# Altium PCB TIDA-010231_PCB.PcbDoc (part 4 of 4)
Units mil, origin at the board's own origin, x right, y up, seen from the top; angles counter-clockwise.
Board outline 3937.01 x 3740.16 mil, 4 copper layers (Top Layer, Signal Layer 1, Signal Layer 2, Bottom Layer), stack 65.355 mil thick; 295 components, 163 nets, 818 pads, 213 vias.
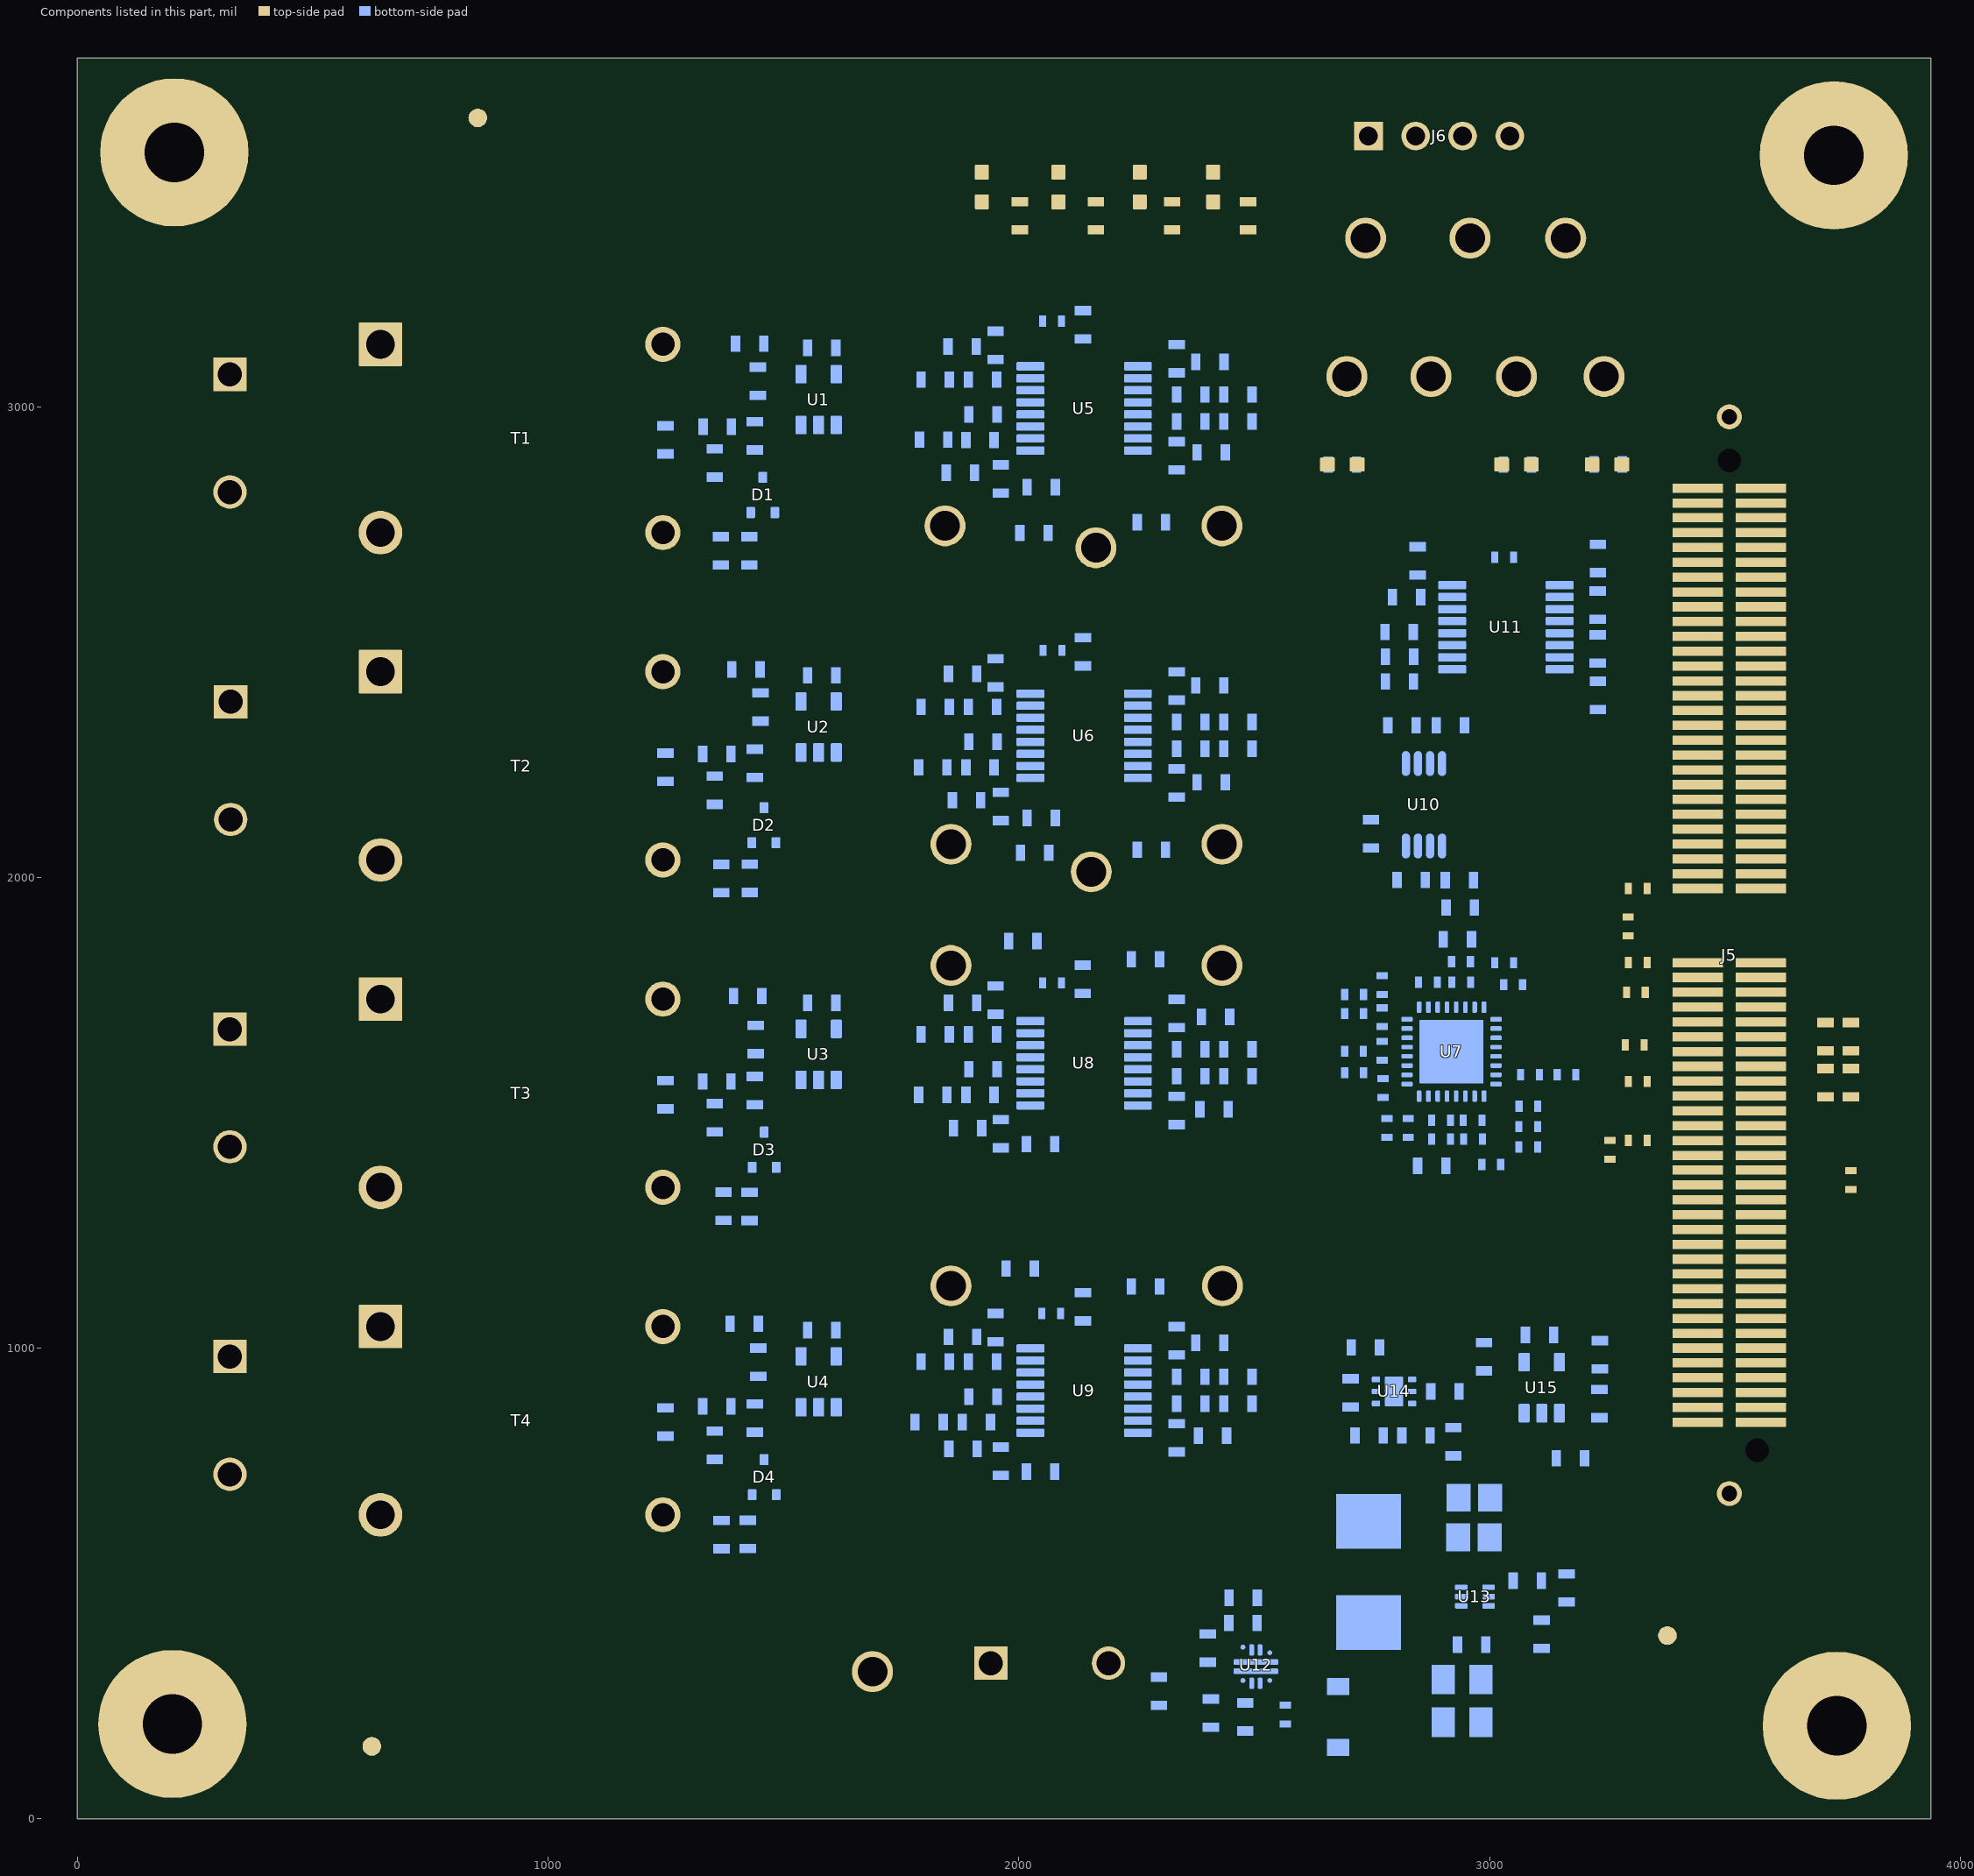
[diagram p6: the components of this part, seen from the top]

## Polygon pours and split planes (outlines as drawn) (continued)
NetC73_2 on Bottom Layer "BOTTOM_LAYER_NETC73_2_P401" (solid, remove dead copper, pour order 401): 2953.13,478.2 2953.13,466.26 2953.1,466.23 2952.97,466.36 2922.81,466.36 2840.31,383.86 2840.31,359.94 2692.08,359.94 2692,359.87 2692,477.12
GND on Bottom Layer "BOTTOM_LAYER_GND_P402" (solid, remove dead copper, pour order 402): 3097.94,573.68 3098.31,573.32 3143.73,573.32 3143.73,710.59 2976.95,710.59 2976.95,551.64 2894.76,551.64 2894.76,514.52 2922.32,486.96 2953.31,486.96 2957.63,482.64 2957.63,165.13 3191.88,165.13 3191.88,390.3 3098.57,390.3 3050.14,438.73 2976.95,438.73 2976.95,505.66 3029.93,505.66
NetC84_1 on Bottom Layer "BOTTOM_LAYER_NETC84_1_P398" (solid, pour order 398): 2553.65,235.54 2553.65,248.95 2525.4,277.19 2525.4,298.9 2557.77,298.9 2579.89,276.77 2579.89,235.54
GND on Bottom Layer "BOTTOM_LAYER_GND_P425" (solid, remove dead copper, pour order 425): 3307.87,2568.6 3221.36,2568.6 3181.29,2528.53 3111.39,2528.53 3111.39,2606.57 3108.88,2609.08 2963.66,2609.08 2963.66,2456.53 2964.7,2455.49 3106.68,2455.49 3106.68,2495.25 3123.2,2511.77 3199.78,2511.77 3222,2489.55 3308.14,2489.55
3V3 on Bottom Layer "BOTTOM_LAYER_3V3_P420" (solid, remove dead copper, pour order 420): 3114.42,1035.32 3104.82,1044.92 3104.82,1093.03 3260.4,1093.03 3260.4,993.13 3218.44,993.13 3172.98,947.67 3126.31,947.67 3114.42,959.57
GND on Bottom Layer "BOTTOM_LAYER_GND_P419" (solid, remove dead copper, pour order 419): 3024.94,1916.26 3024.94,2342.01 2889.01,2342.01 2889.01,2206.39 2726.94,2206.39 2726.94,2110.57 2955.87,2110.57 2976.96,2089.48 2974.77,2087.3 2974.77,2013.76 2955.87,2013.76 2955.87,1916.26
2V5 on Bottom Layer "BOTTOM_LAYER_2V5_P416" (solid, pour order 416): 2874.5,1712.44 2874.5,1745.75 2854.89,1765.36 2854.89,1804.19 2840.69,1804.19 2840.69,1718.34 2846.6,1712.44
NetC77_1 on Bottom Layer "BOTTOM_LAYER_NETC77_1_P411" (solid, pour order 411): 2826.94,887.91 2827.02,887.98 2847.15,887.98 2892.76,842.37 2940.86,842.37 2940.86,794.84 2840.24,794.84 2840.24,852.84 2826.41,866.66 2826.41,888.65
5V25 on Bottom Layer "Bottom Layer-5V25" (solid, pour order 410): 2641.24,568.78 2959.4,568.78 2959.4,737.66 3172.98,737.66 3172.98,790.25 2860.12,790.25 2860.12,744.11 2643.11,744.11 2641.24,745.98
GND on Bottom Layer "BOTTOM_LAYER_GND_P407" (solid, remove dead copper, pour order 407): 3296.14,892.1 3135.44,892.1 3122.55,879.21 3122.55,843.46 3100.2,843.46 3098.71,844.95 3099.91,846.14 3099.91,879.81 3090.07,889.64 2967.92,889.64 2967.92,980.2 3047.47,980.2 3047.47,947.73 3059.09,936.11 3171.7,936.11 3199.43,963.84 3296.14,963.84
GND on Bottom Layer "BOTTOM_LAYER_GND_P403" (solid, pour order 403): 2761.59,859.99 2778.46,876.86 2778.46,915.6 2764.8,929.27 2750.14,929.27 2750.14,1021.18 2817.62,1021.18 2817.62,861.56 2826.94,852.23 2826.53,851.82 2826.53,759.79 2761.59,759.79
NetC74_1 on Bottom Layer "BOTTOM_LAYER_NETC74_1_P399" (solid, remove dead copper, pour order 399): 2930.18,337.51 2944.06,351.39 2944.06,438.81 2952.84,447.59 2951.8,448.64 2951.8,459.29 2927.81,459.29 2849.59,381.07 2849.59,337.51 2768.99,337.51 2750.61,319.13 2456.57,319.13 2456.57,307.57 2589.28,307.57 2687.97,208.88 2809.07,208.88 2852.85,165.1 2930.18,165.1
NetC83_1 on Bottom Layer "BOTTOM_LAYER_NETC83_1_P395" (solid, pour order 395): 2435,241.35 2388.21,241.35 2388.21,261.45 2426.51,299.75 2479.83,299.75 2481.8,297.78 2481.8,288.14
GND on Bottom Layer "BOTTOM_LAYER_GND_P397" (solid, remove dead copper, pour order 397): 2541.54,221.76 2541.54,252.04 2517.1,276.48 2517.1,298.54 2515.9,299.75 2509.55,299.75 2508.37,298.57 2508.37,208.88 2068.49,208.88 2004.61,272.77 2004.61,374.45 1881.85,374.45 1879.82,122.41 2794.06,122.41 2794.06,189.04 2622.89,189.04 2590.18,221.76
Vin on Bottom Layer "BOTTOM_LAYER_VIN_P393" (solid, remove dead copper, pour order 393): 2149.06,372.76 2153.22,368.6 2407.9,368.6 2437.56,338.94 2544.79,338.94 2544.79,327.11 2544.75,327.07 2544.56,327.26 2437.47,327.26 2400.11,289.91 2149.06,289.91
NetR104_1 on Bottom Layer "BOTTOM_LAYER_NETR104_1_P392" (solid, remove dead copper, pour order 392): 2480.94,347.29 2480.67,347.57 2435.94,347.57 2404.86,378.66 2381.4,378.66 2381.4,429.17 2458.17,429.17 2458.17,393.08 2480.94,370.32
GND on Bottom Layer "BOTTOM_LAYER_GND_P391" (solid, remove dead copper, pour order 391): 2115.4,1763.27 2206.14,1763.27 2206.14,1414.61 2066.85,1414.61 2066.85,1642.32 2115.4,1690.86
GND on Bottom Layer "BOTTOM_LAYER_GND_P390" (solid, remove dead copper, pour order 390): 2115.4,1064.46 2206.14,1064.46 2206.14,719.09 2066.85,719.09 2066.85,946.81 2115.4,995.35
GND on Bottom Layer "BOTTOM_LAYER_GND_P387" (solid, remove dead copper, pour order 387): 2115.4,2459.2 2206.14,2459.2 2206.14,2106.56 2066.85,2106.56 2066.85,2337.83 2115.4,2386.37
GND on Bottom Layer "BOTTOM_LAYER_GND_P386" (solid, remove dead copper, pour order 386): 2115.4,3151 2206.14,3151 2206.14,2810.89 2066.85,2810.89 2066.85,3033.34 2115.4,3081.88
CH4- on Bottom Layer "BOTTOM_LAYER_CH4-_P381" (solid, remove dead copper, pour order 381): 285.97,769.93 692.85,769.93 692.85,596.87 285.97,596.87
CH3- on Bottom Layer "BOTTOM_LAYER_CH3-_P377" (solid, remove dead copper, pour order 377): 285.97,1465.47 692.85,1465.47 692.85,1292.41 285.97,1292.41
CH1- on Bottom Layer "BOTTOM_LAYER_CH1-_P373" (solid, remove dead copper, pour order 373): 285.97,2856.55 692.85,2856.55 692.85,2683.48 285.97,2683.48
CH2- on Bottom Layer "BOTTOM_LAYER_CH2-_P369" (solid, remove dead copper, pour order 369): 287.59,2161.01 694.47,2161.01 694.47,1987.94 287.59,1987.94
CH4+ on Bottom Layer "BOTTOM_LAYER_CH4+_P362" (solid, remove dead copper, pour order 362): 287.4,944.88 694.29,944.88 694.29,1091.55 287.4,1091.55
CH3+ on Bottom Layer "BOTTOM_LAYER_CH3+_P358" (solid, remove dead copper, pour order 358): 287.4,1640.42 694.29,1640.42 694.29,1787.09 287.4,1787.09
CH2+ on Bottom Layer "BOTTOM_LAYER_CH2+_P354" (solid, remove dead copper, pour order 354): 289.03,2335.96 695.91,2335.96 695.91,2482.63 289.03,2482.63
CH1+ on Bottom Layer "BOTTOM_LAYER_CH1+_P349" (solid, remove dead copper, pour order 349): 287.4,3031.5 694.29,3031.5 694.29,3178.17 287.4,3178.17
CT1_OUT- on Bottom Layer "BOTTOM_LAYER_CT1_OUT-_P348" (solid, remove dead copper, pour order 348): 1176.65,2650.42 1176.65,2908.7 1311.07,2908.7 1352.98,2866.79 1370.9,2866.79 1422.07,2815.62 1495.51,2815.62 1495.51,2710 1421.19,2710 1327.09,2710 1327.09,2649.53
5V on Signal Layer 2 "SIGNAL_LAYER_2_5V_P191" (solid, pour order 191): 2906.42,1484.47 2917.21,1495.26 2917.21,1871.26 2771.65,1871.26 2771.65,3157.92 1556.97,3159.01 1556.97,809.33 2906.42,809.33
5V25 on Signal Layer 2 "SIGNAL_LAYER_2_5V25_P421" (solid, pour order 421): 2934.1,744.11 3830.1,744.11 3874.02,788.03 3874.02,3017.36 3748.66,3017.36 3748.66,852.84 3245.38,852.84 3195.2,802.66 2932.49,802.66
3V3 on Signal Layer 2 "Signal Layer 2-3V3" (solid, remove dead copper, pour order 438): 1185.72,719.09 1378.06,719.09 1386.28,727.31 1362.53,751.06 1362.53,3373.03 3014.91,3373.03 3039.1,3348.84 3039.1,1886.4 2926.43,1773.73 2926.43,858.59 3737.8,858.59 3737.8,2974.15 3170.67,3541.27 1185.72,3541.27
2V5 on Signal Layer 2 "SIGNAL_LAYER_2_2V5_P192" (solid, pour order 192): 3024.28,2251.1 3024.28,3344.49 1386.79,3344.49 1396.11,480.32 1548.67,480.32 1548.67,3173.13 2794.16,3173.13 2794.16,1881.25 3024.28,1881.25
CH4- on Signal Layer 2 "SIGNAL_LAYER_2_CH4-_P379" (solid, remove dead copper, pour order 379): 286.73,769.17 693.62,769.17 693.62,596.1 286.73,596.1
CH3- on Signal Layer 2 "SIGNAL_LAYER_2_CH3-_P375" (solid, remove dead copper, pour order 375): 286.73,1464.7 693.62,1464.7 693.62,1291.64 286.73,1291.64
CH1- on Signal Layer 2 "SIGNAL_LAYER_2_CH1-_P371" (solid, remove dead copper, pour order 371): 286.73,2855.78 693.62,2855.78 693.62,2682.72 286.73,2682.72
CH2- on Signal Layer 2 "SIGNAL_LAYER_2_CH2-_P367" (solid, remove dead copper, pour order 367): 288.36,2160.24 695.24,2160.24 695.24,1987.18 288.36,1987.18
CH4+ on Signal Layer 2 "SIGNAL_LAYER_2_CH4+_P364" (solid, remove dead copper, pour order 364): 287.4,944.88 694.29,944.88 694.29,1091.55 287.4,1091.55
CH3+ on Signal Layer 2 "SIGNAL_LAYER_2_CH3+_P360" (solid, remove dead copper, pour order 360): 287.4,1640.42 694.29,1640.42 694.29,1787.09 287.4,1787.09
CH2+ on Signal Layer 2 "SIGNAL_LAYER_2_CH2+_P356" (solid, remove dead copper, pour order 356): 289.03,2335.96 695.91,2335.96 695.91,2482.63 289.03,2482.63
CH1+ on Signal Layer 2 "SIGNAL_LAYER_2_CH1+_P352" (solid, remove dead copper, pour order 352): 287.4,3031.5 694.29,3031.5 694.29,3178.17 287.4,3178.17
GND on Signal Layer 1 "Signal Layer 1-GND" (solid, pour order 198): 3263.35,3623.8 3874.02,3008.47 3874.02,683.71 3229.68,39.37 1185.72,39.37 1183.61,3623.8
CH4- on Signal Layer 1 "SIGNAL_LAYER_1_CH4-_P378" (solid, remove dead copper, pour order 378): 285.78,770.34 692.66,770.34 692.66,597.28 285.78,597.28
CH3- on Signal Layer 1 "SIGNAL_LAYER_1_CH3-_P374" (solid, remove dead copper, pour order 374): 285.78,1465.88 692.66,1465.88 692.66,1292.82 285.78,1292.82
CH1- on Signal Layer 1 "SIGNAL_LAYER_1_CH1-_P370" (solid, remove dead copper, pour order 370): 285.78,2856.96 692.66,2856.96 692.66,2683.89 285.78,2683.89
CH2- on Signal Layer 1 "SIGNAL_LAYER_1_CH2-_P366" (solid, remove dead copper, pour order 366): 287.4,2161.42 694.29,2161.42 694.29,1988.35 287.4,1988.35
CH4+ on Signal Layer 1 "SIGNAL_LAYER_1_CH4+_P363" (solid, remove dead copper, pour order 363): 287.4,944.88 694.29,944.88 694.29,1091.55 287.4,1091.55
CH3+ on Signal Layer 1 "SIGNAL_LAYER_1_CH3+_P359" (solid, remove dead copper, pour order 359): 287.4,1640.42 694.29,1640.42 694.29,1787.09 287.4,1787.09
CH2+ on Signal Layer 1 "SIGNAL_LAYER_1_CH2+_P355" (solid, remove dead copper, pour order 355): 289.03,2335.96 695.91,2335.96 695.91,2482.63 289.03,2482.63
CH1+ on Signal Layer 1 "SIGNAL_LAYER_1_CH1+_P351" (solid, remove dead copper, pour order 351): 287.4,3031.5 694.29,3031.5 694.29,3178.17 287.4,3178.17

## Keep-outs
Keep-Out Layer:
  text ".Layer_Name" at 577,-858.49 h60

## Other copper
Top Layer:
  text ".Layer_Name" at 577,-858.49 h60
Signal Layer 1:
  text ".Layer_Name" at 577,-858.49 h60
Signal Layer 2:
  text ".Layer_Name" at 577,-858.49 h60
Bottom Layer:
  text ".Layer_Name" at 577,-858.49 h60

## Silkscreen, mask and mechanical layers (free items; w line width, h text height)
Top Overlay:
  text "TIDA-0100231" at 1822.31,3620.72 h108.27
  text "Danger High Voltage" at 406.07,3344.49 h78.74
  text "CH1: 1kV/10A max" at 141.73,3259.75 h78.74
  text "5V" at 2651.87,2924.35 h39.37
  text "2.5V" at 2817.31,2924.35 h39.37
  text "3.3V" at 3006.88,2924.35 h39.37
  text "5.3V" at 3199.55,2924.35 h39.37
  text "CH1_ / Filt_In" at 1554.64,2629.16 h39.37
  text "GND" at 2119.72,2572.98 h39.37
  text "CH2: 1kV/10A max" at 141.73,2551.18 h78.74
  text "CH1_ / Filt_Out" at 2332.52,2521.46 h39.37
  text "CH2_ / Filt_Out" at 2512.72,2039.46 h39.37
  text "CH2_ / Filt_In" at 1574.69,1945.72 h39.37
  text "GND" at 2105.15,1881.26 h39.37
  text "CH3: 1kV/10A max" at 141.73,1858.27 h78.74
  text "CH3_ / Filt_In" at 1937.16,1767.93 h39.37
  text "CH3_ / Filt_Out" at 2516.27,1703.18 h39.37
  text "CH4: 1kV/10A max" at 141.73,1157.48 h78.74
  text "CH4_ / Filt_In" at 1945.7,1071.85 h39.37
  text "CH4_ / Filt_Out" at 2512.72,1067.69 h39.37
  text "GND" at 1866.22,542.58 h39.37
  text "Vin:  / 8V to 16V" at 2162.58,530.3 h39.37
  text "GND" at 1631,171.48 h39.37
  text ".Layer_Name" at 577,-858.49 h60
Bottom Overlay:
  lines w10: 1786.21,2398.13 1904.11,2398.13 1911.17,2391.07 1911.17,2389.58 ; 1786.21,3109.67 1804.3,3091.57 1843.07,3091.94 1887.4,3091.94 ; 1793.76,1701.72 1874.15,1701.71 1879.45,1696.41 1879.45,1694.48 ; 1810.8,2893.82 1902.68,2893.82 1908.15,2893.82 1913.78,2899.45 ; 1818.77,2192.79 1818.77,2192.21 1826.91,2200.35 1909.45,2200.35 ; 1834.65,2397.92 1834.85,2398.13 ; 1840.16,1498.18 1851.04,1509.06 1895.2,1509.06 ; 1922.2,2051.46 1922.2,2085.08 ; 1924.38,2087.26 1928.73,2091.61 1930.91,2093.79 ; 1934.15,2097.27 1936.33,2099.44 ; 1964.9,2753.55 1971.08,2759.73 1971.08,2791.97 ; 2371.04,1662.98 2377.27,1669.21 2379.34,1669.21 2389.35,1669.21 2457.27,1669.21 ; 2374.36,971.23 2450.11,971.23 ; 2375.46,850.54 2444.8,850.54 ; 2379.99,2359.94 2437.91,2359.94 2472.76,2394.79 ; 2386.49,2242.42 2451.2,2242.42 2464.97,2228.65 ; 2388.21,436.23 2404.22,420.22 2422.73,420.22 ; 2408.31,3056.88 2447.32,3056.88 2483.18,3092.74 ; 2410.29,971.23 2450.11,971.23 ; 2411.41,1550.24 2411.41,1549.92 2423.62,1537.71 2463.97,1537.71 2483.77,1517.91 ; 2412.64,2939.17 2450.38,2939.17 2457.27,2932.28 ; 2479.36,1522.32 2488.18,1513.5 ; 2483.11,1017.79 2483.11,1004.23 ; 2483.96,969.11 2492.42,969.11 2509.75,986.45 ; 2516.32,1583.24 2552.31,1583.24 2554.79,1580.76 2554.79,1570.41 ; 2548.06,1720.6 2567.31,1701.35 2664.89,1701.35 2679.06,1687.71 2748.99,1687.71 ; 2585.2,1953.01 2586.61,1951.6 2491.32,1951.6 2491.32,1833.38 2520.26,1833.38 2698.23,1833.38 2702.8,1837.95 2702.8,1966.48 2702.8,1975.79 2702.8,2031.65 2586.73,2031.65 ; 2585.91,1952.31 2585.91,2030.83 ; 2690.47,1662.98 2738.42,1662.98 2743.67,1657.73 2746.63,1657.73 ; 2704.01,1921.26 2702.8,1920.04 2753.14,1920.04 2753.14,1917.24 2753.4,1917.24 2818.26,1852.38 2788.63,1852.61 ; 2709.22,1497.38 2720.09,1508.26 2727.05,1508.26 2748.04,1526.9 ; 2739.47,1310.7 2931.57,1310.7 2949.93,1329.07 2949.93,1376.41 2949.93,1417.61 ; 2763.78,1819.34 2770.33,1812.79 2770.33,1812.56 2770.33,1808.82 ; 2768.36,1985.89 2780.17,1985.89 ; 2817.23,1883.41 2817.54,1852.21 ; 2851.34,759.79 2851.34,780.27 ; 2852.49,998.97 2852.49,968.26 2880.38,940.37 ; 2854.55,355.33 2867.1,367.89 2910,367.89 ; 2949.93,1417.97 2949.93,1417.66 ; 3053.28,703.95 3163.43,703.95 ; 3059.42,581.22 3163.43,581.22 ; 3094.4,1639.56 3094.5,1639.56 3098.07,1635.99 3098.07,1610.57 ; 3123.13,1517.94 3156.71,1484.36 ; 3123.53,1472.38 3139.22,1472.38 3152.94,1458.66 3162.82,1448.78 ; 3168.84,1601.45 3229.93,1662.39 ; 2450.11,971.23 2483.11,1004.23 ; 2450.11,971.23 2483.11,1004.23 ; 2949.93,1417.61 2937.83,1405.51 2949.93,1417.61 ; 2949.93,1417.61 2949.93,1417.66 ; 2949.93,1417.66 2962.79,1404.8 2949.93,1417.66 ; 2502.58,1240.16 2528.2,1240.16 2739.47,1240.16 2739.47,1263.24 2739.47,1358.16 2703.61,1358.16 2502.58,1358.16 2502.58,1240.16 ; 2829.7,1749.89 2829.7,1845.55 2876.06,1845.55 2876.06,1902.47 2984.45,1902.47 2984.45,1749.89 2829.7,1749.89 ; 2856.72,1420.74 3010.69,1420.74 3010.69,1509.54 2856.72,1509.54 2856.72,1420.74
  text ".Layer_Name" at 577,-858.49 h60
Top Paste:
  text ".Layer_Name" at 577,-858.49 h60
Bottom Paste:
  text ".Layer_Name" at 577,-858.49 h60
Top Solder:
  text ".Layer_Name" at 577,-858.49 h60
  text ".Layer_Name" at 577,-858.49 h60
Bottom Solder:
  text ".Layer_Name" at 577,-858.49 h60
Drill Guide:
  text ".Layer_Name" at 577,-858.49 h60
M1 Board Outline:
  the board outline again, w10
  text ".Layer_Name" at 577,-858.49 h60
M2 Board Dimensions:
  rectangle: 0,-275 125,-150
  rectangle: 125,-400 500,-275
  lines w7: 0,-271.06 1000,-271.06 ; 0,-146.06 0,-396.06 1000,-396.06 1000,-146.06 ; 0,-98.82 1000,-98.82 ; 125,-396.06 125,-146.06 ; 250,-396.06 250,-146.06 ; 500,-396.06 500,-146.06 ; 750,-396.06 750,-146.06
  text ".Layer_Name" at 577,-858.49 h60
M3 3D STEP Top:
  text ".Layer_Name" at 577,-858.49 h60
M4 3D STEP Bottom:
  text ".Layer_Name" at 577,-858.49 h60
M5 Assembly Top:
  lines w10: -292,-930.17 6308,-930.17 ; -292,-726.83 6310,-726.83 ; -292,-523.5 -292,-1133.5 3713,-1133.5 6310,-1133.5 6310,-523.5 -291.5,-523.5 -291.5,-1133.5 1284,-1133.5 ; 2173,-1133.5 2173,-523.5 ; 3440,-726.83 3440,-523.5 ; 4280,-726.83 4280,-523.5 ; 4902,-1140 4902,-937.17
  text "COMPONENTS MARKED 'DNP' SHOULD NOT BE POPULATED." at 1153.5,-318.5 h60
  text "ASSEMBLY VARIANT:" at 1153,-434 h60
  text ".VariantName" at 2189,-434 h60
  text "PCB VIEWED FROM TOP SIDE" at -228.5,-655.67 h60
  text "BOARD #:" at 2248,-655.67 h60
  text ".PRJ_Number" at 2793.5,-655.67 h60
  text "REV:" at 3638,-655.67 h60
  text ".PCB_Rev" at 3929.5,-655.67 h60
  text "SVN REV:" at 4476,-655.67 h60
  text ".VersionControl_RevNumber" at 4982,-655.67 h60
  text "TID #:" at 2248,-859 h60
  text ".TID" at 2793.5,-859 h60
  text "PLOT NAME =" at -228.5,-1064.34 h60
  text ".plot_File_Name" at 577,-1064.34 h60
  text "GENERATED    :" at 2250,-1064.34 h60
  text ".Print_Date" at 3119.5,-1064.34 h60
  text ".Print_Time" at 3848.5,-1064.34 h60
  text "TEXAS INSTRUMENTS" at 5113,-1064.34 h60
M6 Assembly Bottom:
  lines w10: -292.5,-727.33 6309.5,-727.33 ; -290.5,-930.67 6309.5,-930.67 ; 1115.5,-1140.5 1115.5,-937.67 ; 1737.5,-727.33 1737.5,-524 ; 2577.5,-727.33 2577.5,-524 ; 3844.5,-1134 3844.5,-524 ; 4733.5,-1134 6309,-1134 6309,-524 -292.5,-524 -292.5,-1134 2304.5,-1134 6309.5,-1134 6309.5,-524
  text "COMPONENTS MARKED 'DNP' SHOULD NOT BE POPULATED." at 6102,-318 h60
  text ".VariantName" at 5058,-434 h60
  text "ASSEMBLY VARIANT:" at 6097,-434 h60
  text ".VersionControl_RevNumber" at 1035.5,-656.17 h60
  text "SVN REV:" at 1541.5,-656.17 h60
  text ".PCB_Rev" at 2088,-656.17 h60
  text "REV:" at 2379.5,-656.17 h60
  text ".PRJ_Number" at 3224,-656.17 h60
  text "BOARD #:" at 3769.5,-656.17 h60
  text "PCB VIEWED FROM BOTTOM SIDE" at 6246,-656.17 h60
  text ".TID" at 3224,-859.5 h60
  text "TID #:" at 3769.5,-859.5 h60
  text "TEXAS INSTRUMENTS" at 904.5,-1064.84 h60
  text ".Print_Time" at 2169,-1064.84 h60
  text ".Print_Date" at 2898,-1064.84 h60
  text "GENERATED    :" at 3767.5,-1064.84 h60
  text ".plot_File_Name" at 5440.5,-1064.84 h60
  text "PLOT NAME =" at 6246,-1064.84 h60
M9 Title Sheet:
  drawing of 57 lines, arcs and shapes, not listed
  text "1" at 739.84,8036.5 h70
  text "2" at 3235.5,8036.5 h70
  text "3" at 5724.84,8036.5 h70
  text "4" at 8231.51,8036.5 h70
  text "5" at 10730.5,8036.5 h70
  text "6" at 13235.5,8036.5 h70
  text "A" at -416.5,6893.5 h70
  text "A" at 14383.5,6893.5 h70
  text "B" at -416.5,4513.5 h70
  text "B" at 14383.5,4513.5 h70
  text "C" at -416.5,2138.5 h70
  text "C" at 14383.5,2138.5 h70
  text "PROJECT TITLE:" at 11343.5,277.5 h45
  text ".PRJ_Title" at 11393.5,144.17 h70
  text "DESIGNED FOR:" at 11343.5,-23.5 h45
  text ".PRJ_Customer" at 11393.5,-163.5 h70
  text "D" at -416.5,-231.5 h70
  text "D" at 14383.5,-231.5 h70
  text "FILE NAME:" at 11343.5,-323.5 h45
  text ".PCB_File_Name_No_Path" at 11393.5,-443.5 h70
  text "Texas Instruments (TI) and/or its licensors do not warrant the accuracy or completeness of this specification" at 6374,-605.34 h45
  text "ENGINEER:" at 11343.5,-613.5 h45
  text "LAYOUT BY:" at 12848.5,-613.5 h45
  text "or any information contained therein. TI and/or its licensors do not warrant that this design will meet" at 6329.01,-718 h45
  text ".PRJ_Engineer" at 11393.5,-768.49 h70
  text ".PCB_Layout" at 12899,-768.49 h70
  text "the specifications, will be suitable for your application or fit for any particular purpose, or will operate in" at 6329.01,-830.67 h45
  text ".Layer_Name" at 577,-858.49 h60
  text "ALTIUM DESIGNER VERSION:" at 12848.5,-923.5 h45
  text "an implementation. TI and/or its licensors do not warrant that the design is production worthy. You should" at 6329.01,-943.33 h45
  text "completely validate and test your design implementation to confirm the system functionality for your application." at 6374,-1056 h45
  text ".print_Scale" at 11393.5,-1056.83 h70
  text ".Application_BuildNumber" at 12899,-1056.83 h70
  text "1" at 739.84,-1263.5 h70
  text "2" at 3235.5,-1263.5 h70
  text "3" at 5724.84,-1263.5 h70
  text "4" at 8231.51,-1263.5 h70
  text "5" at 10730.5,-1263.5 h70
  text "6" at 13235.5,-1263.5 h70
M10 Fab Notes:
  drawing of 189 lines, arcs and shapes, not listed
  text "DESIGN INFORMATION" at 12382.02,6356.17 h60
  text "MIN. TRACK WIDTH:" at 11737.46,6224.05 h60
  text "8" at 12833.7,6224.05 h60
  text "MIL" at 12988.46,6224.05 h60
  text "MIN. CLEARANCE:" at 11737.46,6099.92 h60
  text "0.2" at 12773.7,6099.93 h60
  text "mm" at 12988.46,6099.92 h60
  text "MIN. VIA PAD SIZE:" at 11737.46,5975.8 h60
  text "20" at 12803.71,5975.8 h60
  text "MIL" at 12988.46,5975.8 h60
  text "0.05mm (2MIL)" at 12432.46,5845.9 h60
  text "MINIMUM ANNULAR RING" at 11408.23,5837.67 h60
  text "EXTERNAL" at 13140.46,5837.67 h60
  text "PER" at 11608.23,5727.55 h60
  text "IPC-D-275 CLASS 2 LEVEL C" at 11828.23,5727.54 h60
  text "MIL, HOLES" at 13316.46,5627.07 h60
  text "+/-" at 12924,5618.48 h60
  text "+/-" at 13778,5618.48 h60
  text "REGISTRATION TOLERANCES:" at 11408.23,5617.42 h60
  text "METAL" at 12608,5617.42 h60
  text "5" at 13184.2,5617.42 h60
  text "3" at 14017.2,5617.42 h60
  text "MIL" at 14133.46,5617.42 h60
  text "HOLE SIZE TOLERANCE (UNLESS OTHERWISE SPECIFIED):" at 11408.23,5519.1 h60
  text "+/-" at 13778,5516.23 h60
  text "3" at 14017.2,5515.17 h60
  text "MIL" at 14133.46,5515.17 h60
  text "MATERIAL:" at 11333.46,5377.52 h60
  text "FR-4 High Tg" at 12319.9,5249 h60
  text "X" at 12175.46,5241.01 h60
  text "FR-408" at 11754.46,5236.49 h60
  text "OTHER" at 13242.46,5236.49 h60
  text "62 MIL (1.6mm) +/-10%" at 12074.56,5093.46 h60
  text "X" at 11954.46,5091.01 h60
  text "THICKNESS:" at 11408.23,5085.24 h60
  text "OTHER" at 13359.46,5085.24 h60
  text "TOLERANCE:" at 11408.23,4946.92 h60
  text "X" at 12256.46,4946.92 h60
  text "ANSI IPC-6012 TYPE 3 CLASS 2" at 12434.48,4946.92 h60
  text "OTHER +/-" at 12434.46,4802.73 h60
  text "BOW & TWIST:" at 11408.23,4657.54 h60
  text "X" at 12256.46,4657.54 h60
  text "ANSI IPC-6012 TYPE 3 CLASS 2" at 12434.48,4657.54 h60
  text "OTHER +/-" at 12434.46,4510.85 h60
  text "DRILLING:" at 11333.46,4380.23 h60
  text "NC_DRILL FILES" at 13094.46,4275.04 h60
  text "REFERENCE:" at 11408.23,4271.1 h60
  text "X" at 12065.46,4271.01 h60
  text "AS SHOWN" at 12243.46,4271.1 h60
  text "X" at 12966.46,4271.1 h60
  text "OTHER" at 13392.46,4128.85 h60
  text "PTH COPPER THICKNESS:" at 11407.91,4125.32 h60
  text "X" at 12547.14,4125.32 h60
  text "20-30 um" at 12675.14,4125.32 h60
  text "BOARD FINISH:" at 11333.46,3977.73 h60
  text "SILKSCREEN:" at 11488.68,3867.6 h60
  text "X" at 12446.46,3867.6 h60
  text "TOP" at 12563.46,3867.6 h60
  text "X" at 12956.46,3867.6 h60
  text "BOTTOM" at 13074.46,3867.6 h60
  text "SILKSCREEN COLOR:" at 11488.68,3712.41 h60
  text "X" at 12445.46,3712.41 h60
  text "WHITE" at 12563.46,3712.41 h60
  text "OTHER" at 13074.46,3712.41 h60
  text "X" at 12576.46,3568.96 h60
  text "GREEN" at 12694.46,3568.96 h60
  text "OTHER" at 13312.46,3568.96 h60
  text "SOLDER RESIST COLOR:" at 11488.68,3562.1 h60
  text "X" at 12576.46,3414.71 h60
  text "MATTE" at 12694.46,3414.71 h60
  text "SEMI-GLOSS" at 13312,3414.07 h60
  text "IMMERSION GOLD (ENIG)" at 12394.46,3241.94 h60
  text "ENEPIG" at 13732,3234.72 h60
  text "SURFACE FINISH:" at 11333.46,3233.72 h60
  text "X" at 12216.46,3233.72 h60
  text "IMM. TIN/SILVER OR EQUIV" at 11663,3096.4 h60
  text "OTHER" at 13094.46,3092.47 h60
  text "ARRAY/PANEL:" at 11333.46,2937.09 h60
  text "CUT AND TRIM PER M1 BOARD OUTLINE" at 12394.46,2928.87 h60
  text "N.C. ROUTE" at 12394.46,2792.9 h60
  text "X" at 13082.46,2792.9 h60
  text "V. SCORE" at 13260.46,2792.9 h60
  text "CERTIFICATION:" at 11333.46,2663.77 h60
  text "MATERIALS AND WORKMANSHIP FOR ALL PCBS" at 12058.46,2663.77 h60
  text "TO MEET OR EXCEED THE REQUIREMENTS OF:" at 12058.46,2569.71 h60
  text "X" at 11695.97,2441.08 h60
  text "ANSI IPC-A-600F CLASS ->" at 11823.96,2441.08 h60
  text "X" at 13471.97,2441.08 h60
  text "2" at 13581.96,2441.08 h60
  text "1" at 13266.96,2439.58 h60
  text "3" at 13935.96,2439.58 h60
  text "X" at 12507.97,2293.39 h60
  text "RoHS" at 12635.96,2293.39 h60
  text "OTHER" at 13280.36,2293.39 h60
  text "PER ORDER" at 13677.42,2293.39 h60
  text "ALL BOARDS MUST MEET OR EXCEED UL94-V0 REQUIREMENTS." at 11361,2139.57 h60
  text "PCB MUST BEAR THE UL94V-0 UL REGISTERED MATERIAL ID NUMBER" at 11361,2023.5 h60
  text "ADDITIONAL REQUIREMENTS:" at 11333.46,1854.08 h60
  text "MICROSECTION:" at 11408.23,1746.95 h60
  text "YES" at 12313.96,1746.95 h60
  text "REQUIRED" at 13175.46,1602.62 h60
  text "BARE BOARD ELEC. TEST:" at 11408.23,1599.76 h60
  text "NONE" at 12713.96,1599.76 h60
  text "X" at 13057.46,1599.76 h60
  text "PER ORDER" at 13767.46,1599.76 h60
  text "XX MIL VIAS REQUIRE NON-CONDUCTIVE FILL AND PLANARIZE" at 11576.38,1394.82 h59
  text "XX MIL VIAS REQUIRE CONDUCTIVE FILL AND PLANARIZE" at 11584.38,1290.84 h60
  text "OUTER XX MIL TRACES REQUIRE 50 OHM SINGLE-ENDED IMPEDANCE" at 11583.39,1127.46 h58
  text "LAYER 2 & 3 (INNER LAYERS) XX MIL WIDE, XX MIL SPACE / TRACES REQUIRE 100 OHM DIFFERENTIAL IMPEDANCE" at 11575.39,891.74 h60
  text ".Layer_Name" at 577,-858.49 h60
M11 Gerber Information:
  lines w10: -292,-930.17 6308,-930.17 ; -292,-726.83 6310,-726.83 ; -292,-523.5 -292,-1133.5 3713,-1133.5 6310,-1133.5 6310,-523.5 -291.5,-523.5 -291.5,-1133.5 1284,-1133.5 ; 2173,-1133.5 2173,-523.5 ; 3440,-726.83 3440,-523.5 ; 4280,-726.83 4280,-523.5 ; 4902,-1140 4902,-937.17
  text "ALL ARTWORK VIEWED FROM TOP SIDE" at -228.5,-655.67 h60
  text "BOARD #:" at 2248,-655.67 h60
  text ".PRJ_Number" at 2793.5,-655.67 h60
  text "REV:" at 3638,-655.67 h60
  text ".PCB_Rev" at 3929.5,-655.67 h60
  text "SVN REV:" at 4476,-655.67 h60
  text ".VersionControl_RevNumber" at 4982,-655.67 h60
  text "LAYER NAME =" at -228.5,-858.49 h60
  text "TID #:" at 2248,-859 h60
  text ".TID" at 2793.5,-859 h60
  text "PLOT NAME =" at -228.5,-1064.34 h60
  text ".plot_File_Name" at 577,-1064.34 h60
  text "GENERATED    :" at 2250,-1064.34 h60
  text ".Print_Date" at 3119.5,-1064.34 h60
  text ".Print_Time" at 3848.5,-1064.34 h60
  text "TEXAS INSTRUMENTS" at 5113,-1064.34 h60
M12 Stackup:
  drawing of 295 lines, arcs and shapes, not listed
  text "Layer" at 9814.08,7835.99 h60
  text "Name" at 10224,7835.99 h60
  text "Material" at 11163.74,7835.99 h60
  text "Thickness" at 12023.51,7835.99 h60
  text "Constant" at 12673.34,7835.99 h60
  text "Board Layer Stack" at 13243.2,7835.99 h60
  text "Top Overlay" at 10224,7715.99 h60
  text "Top Solder" at 10224,7595.99 h60
  text "Solder Resist" at 11163.74,7595.99 h60
  text "0.39mil" at 12023.51,7595.99 h60
  text "3.5" at 12673.34,7595.99 h60
  text "1" at 9814.08,7475.99 h60
  text "Top Layer" at 10224,7475.99 h60
  text "1.38mil" at 12023.51,7475.99 h60
  text "Dielectric 1" at 10224,7355.99 h60
  text "FR-4" at 11163.74,7355.99 h60
  text "6.30mil" at 12023.51,7355.99 h60
  text "4.2" at 12673.34,7355.99 h60
  text "2" at 9814.08,7235.99 h60
  text "Signal Layer 1" at 10224,7235.99 h60
  text "1.38mil" at 12023.51,7235.99 h60
  text "Dielectric 2" at 10224,7115.99 h60
  text "FR-4" at 11163.74,7115.99 h60
  text "47.24mil" at 12023.51,7115.99 h60
  text "4.8" at 12673.34,7115.99 h60
  text "3" at 9814.08,6995.99 h60
  text "Signal Layer 2" at 10224,6995.99 h60
  text "1.38mil" at 12023.51,6995.99 h60
  text "Dielectric 3" at 10224,6875.99 h60
  text "FR-4" at 11163.74,6875.99 h60
  text "6.30mil" at 12023.51,6875.99 h60
  text "4.2" at 12673.34,6875.99 h60
  text "4" at 9814.08,6755.99 h60
  text "Bottom Layer" at 10224,6755.99 h60
  text "1.38mil" at 12023.51,6755.99 h60
  text "Bottom Solder" at 10224,6635.99 h60
  text "Solder Resist" at 11163.74,6635.99 h60
  text "0.39mil" at 12023.51,6635.99 h60
  text "3.5" at 12673.34,6635.99 h60
  text "Bottom Overlay" at 10224,6515.99 h60
  text ".Layer_Name" at 577,-858.49 h60
M13 Component Bodies Top:
  text ".Layer_Name" at 577,-858.49 h60
M14 Component Bodies Bottom:
  text ".Layer_Name" at 577,-858.49 h60
M15 Courtyards Top:
  text ".Layer_Name" at 577,-858.49 h60
M16 Courtyards Bottom:
  text ".Layer_Name" at 577,-858.49 h60
Drill Drawing:
  circle w10: c5129.2,3011.96 r16.54
  circle w10: c5129.2,3011.96 r27.56
  circle w10: c5129.2,2391.83 r27.56
  lines w10: 5101.64,2502.07 5115.42,2502.07 5115.42,2488.29 5142.98,2488.29 5142.98,2502.07 5156.76,2502.07 5156.76,2529.64 5142.98,2529.64 5142.98,2543.42 5115.42,2543.42 5115.42,2529.64 5101.64,2529.64 5101.64,2502.07 ; 5101.64,2639.88 5129.2,2612.32 5156.76,2639.88 5129.2,2667.44 5101.64,2639.88 ; 5101.64,2736.35 5156.76,2736.35 5156.76,2791.47 5101.64,2791.47 5101.64,2736.35 ; 5101.64,2860.37 5101.64,2874.15 5115.42,2887.93 5101.64,2901.72 5101.64,2915.5 5115.42,2915.5 5129.2,2901.72 5142.98,2915.5 5156.76,2915.5 5156.76,2901.72 5142.98,2887.93 5156.76,2874.15 5156.76,2860.37 5142.98,2860.37 5129.2,2874.15 5115.42,2860.37 5101.64,2860.37 ; 5101.64,3122.21 5115.42,3122.21 5129.2,3108.43 5142.98,3122.21 5156.76,3122.21 5142.98,3135.99 5156.76,3149.77 5142.98,3149.77 5129.2,3163.55 5115.42,3149.77 5101.64,3149.77 5115.42,3135.99 5101.64,3122.21 ; 5101.64,3287.58 5156.76,3287.58 5129.2,3232.45 5101.64,3287.58 ; 5101.64,3356.48 5129.2,3370.26 5156.76,3356.48 5142.98,3384.04 5156.76,3411.6 5129.2,3397.82 5101.64,3411.6 5115.42,3384.04 5101.64,3356.48
  lines w12: 5051.66,2327.06 8278.46,2327.06 ; 5051.66,3443.3 8278.46,3443.3 ; 5389.02,2203.03 5389.02,3567.33 ; 5720.71,2203.03 5720.71,3567.33 ; 6356.57,2203.03 6356.57,3567.33 ; 6615.37,2203.03 6615.37,3567.33 ; 6990.12,2203.03 6990.12,3567.33 ; 7712.66,2203.03 7712.66,3567.33 ; 5051.66,2203.03 8278.46,2203.03 8278.46,3567.33 5051.66,3567.33 5051.66,2203.03
  text "Symbol" at 5126.07,3480.51 h72
  text "Quantity" at 5426.23,3480.51 h72
  text "Finished Hole Size" at 5757.92,3480.51 h72
  text "Plated" at 6393.78,3480.51 h72
  text "Hole Type" at 6652.57,3480.51 h72
  text "Drill Layer Pair" at 7027.32,3480.51 h72
  text "Hole Tolerance" at 7749.86,3480.51 h72
  text "2" at 5426.23,3356.48 h60
  text "50.00mil (1.270mm)" at 5757.92,3356.48 h60
  text "NPTH" at 6393.78,3356.48 h60
  text "Round" at 6652.57,3356.48 h60
  text "Top Layer - Bottom Layer" at 7027.32,3356.48 h60
  text "213" at 5426.23,3232.45 h60
  text "7.87mil (0.200mm)" at 5757.92,3232.45 h60
  text "PTH" at 6393.78,3232.45 h60
  text "Round" at 6652.57,3232.45 h60
  text "Top Layer - Bottom Layer" at 7027.32,3232.45 h60
  text "2" at 5426.23,3108.43 h60
  text "33.07mil (0.840mm)" at 5757.92,3108.43 h60
  text "PTH" at 6393.78,3108.43 h60
  text "Round" at 6652.57,3108.43 h60
  text "Top Layer - Bottom Layer" at 7027.32,3108.43 h60
  text "4" at 5426.23,2984.4 h60
  text "40.16mil (1.020mm)" at 5757.92,2984.4 h60
  text "PTH" at 6393.78,2984.4 h60
  text "Round" at 6652.57,2984.4 h60
  text "Top Layer - Bottom Layer" at 7027.32,2984.4 h60
  text "8" at 5426.23,2860.37 h60
  text "49.21mil (1.250mm)" at 5757.92,2860.37 h60
  text "PTH" at 6393.78,2860.37 h60
  text "Round" at 6652.57,2860.37 h60
  text "Top Layer - Bottom Layer" at 7027.32,2860.37 h60
  text "10" at 5426.23,2736.35 h60
  text "51.18mil (1.300mm)" at 5757.92,2736.35 h60
  text "PTH" at 6393.78,2736.35 h60
  text "Round" at 6652.57,2736.35 h60
  text "Top Layer - Bottom Layer" at 7027.32,2736.35 h60
  text "8" at 5426.23,2612.32 h60
  text "61.02mil (1.550mm)" at 5757.92,2612.32 h60
  text "PTH" at 6393.78,2612.32 h60
  text "Round" at 6652.57,2612.32 h60
  text "Top Layer - Bottom Layer" at 7027.32,2612.32 h60
  text "18" at 5426.23,2488.29 h60
  text "63.00mil (1.600mm)" at 5757.92,2488.29 h60
  text "PTH" at 6393.78,2488.29 h60
  text "Round" at 6652.57,2488.29 h60
  text "Top Layer - Bottom Layer" at 7027.32,2488.29 h60
  text "4" at 5426.23,2364.27 h60
  text "125.98mil (3.200mm)" at 5757.92,2364.27 h60
  text "PTH" at 6393.78,2364.27 h60
  text "Round" at 6652.57,2364.27 h60
  text "Top Layer - Bottom Layer" at 7027.32,2364.27 h60
  text "269 Total" at 5426.23,2240.24 h60
  text ".Layer_Name" at 577,-858.49 h60
Mechanical 17:
  text ".Layer_Name" at 577,-858.49 h60
Mechanical 18:
  text ".Layer_Name" at 577,-858.49 h60
Mechanical 19:
  text ".Layer_Name" at 577,-858.49 h60

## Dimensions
0,0 to 0,3740.16 on M2 Board Dimensions
0,0 to 3937.01,-7.87 on M2 Board Dimensions
0,-396.06 to 1000,-396.06 on M2 Board Dimensions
